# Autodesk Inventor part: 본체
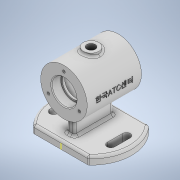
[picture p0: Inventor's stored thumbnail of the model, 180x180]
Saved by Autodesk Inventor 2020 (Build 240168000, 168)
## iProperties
Created: 2021-09
Part Number: 본체
Material: 일반
Document SubType Name: Modeling
Designer: Administrator
Density: 1 g/cm^3
Appearance: 기본값
Mass: 173.2 g
Surface Area: 487.332 cm^2
Volume: 173.2 cm^3
Author: Administrator
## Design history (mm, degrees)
sketch "스케치1"
  geometry: C1 r 52.5 at (0, 0); 1 further point
  constraints: 1 centre point, 1 coincident
  dimensions: "d4" = 105 diameter of C1
extrude "돌출1" new body sketch "스케치1" distance "d1" = 10; taper "d2" = 0 deg
sketch "스케치2"
  geometry: L1 (-81.213, -38.87)-(81.213, -38.87); L2 (81.213, -38.87)-(81.213, 36.13); L3 (81.213, 36.13)-(-81.213, 36.13); L4 (-81.213, 36.13)-(-81.213, -38.87); L5 (-81.213, -38.87)-(81.213, 36.13); L6 (81.213, -38.87)-(-81.213, 36.13); C1 r 52.5 at (0, 0) reference; 6 further points
  constraints: 12 end point, 2 midpoint, 2 parallel, 1 horizontal, 1 perpendicular
  dimensions: "d5" = 75 distance of L2.end L1.end
extrude "돌출2" cut sketch "스케치2" distance "d6" = 10; taper "d7" = 0 deg
sketch "스케치3"
  geometry: C1 r 30 at (0, 62); 1 further point
  constraints: 1 centre point
  dimensions: "d9" = 60 diameter of C1; "d10" = 62 distance of point (0, 0) C1.centre
extrude "돌출3" join sketch "스케치3" stored distance "d11" = 70; taper "d12" = 0 deg
sketch "스케치4"
  geometry: L1 (92, 35)-(32, 35) reference; L2 (62, 35)-(62, -35); L3 (32, -35)-(92, -35) reference; L4 (78, 35)-(78, 23); L5 (78, 23)-(76, 23); L6 (76, 23)-(76, 20); L7 (76, 20)-(87, 20); L8 (87, 20)-(87, -20); L9 (87, -20)-(76, -20); L10 (76, -20)-(76, -23); L11 (76, -23)-(78, -23); L12 (78, -23)-(78, -35); 1 further point
  constraints: 20 end point, 6 perpendicular, 6 point on line, 2 midpoint, 1 vertical
  dimensions: "d13" = 32 diameter of L4 L2; "d14" = 28 diameter of L6 L2; "d15" = 50 diameter of L8 L2; "d16" = 12 distance between parallel lines of L1 L5; "d17" = 12 distance between parallel lines of L3 L11; "d18" = 40 distance between parallel lines of L9 L7; "d19" = 3 distance between parallel lines of L5 L7
revolve "회전1" sketch "스케치4" stored, may be unused: angle "d20" = 90 deg
sketch "스케치5"
  geometry: L1 (-5, 23.63)-(5, 23.63); L2 (5, 23.63)-(5, -26.37); L3 (5, -26.37)-(-5, -26.37); L4 (-5, -26.37)-(-5, 23.63); L5 (35.29, -38.87)-(-35.29, -38.87) reference; A1 r 52.5 centre (0, 0) between (35.29, -38.87) and (38.09, 36.13) reference; A2 r 52.5 centre (0, 0) between (-38.09, 36.13) and (-35.29, -38.87) reference; 1 further point
  constraints: 8 end point, 2 parallel, 1 horizontal, 1 perpendicular
  dimensions: "d21" = 10 distance of L2.end L3.end; "d22" = 50 distance of L1.end L2.end; "d67" = 12.5 distance between parallel lines of L5 L3; "d68" = 47.5 distance edge to line of A2 L4
extrude "돌출4" join sketch "스케치5" stored distance "d11" = 70; taper "d12" = 0 deg; stored distance "d23" = 70; taper "d24" = 0 deg
node "작업 평면2"
  node "작업 평면1"
sketch "스케치6"
  geometry: C1 r 10 at (0, 0); 1 further point
  constraints: 1 centre point, 1 coincident
  dimensions: "d26" = 10 radius of C1
extrude "돌출5" join sketch "스케치6" stored distance "d11" = 70; taper "d12" = 0 deg; stored distance "d27" = 70; taper "d28" = 0 deg
sketch "스케치7"
  geometry: C1 r 10 at (0, 0) reference; 2 further points
  constraints: 1 coincident
hole "구멍1" sketch "스케치7" at (0, 0) diameter "d29" = 10.917; stored, may be unused: countersink angle "d33" = 90 deg, drill point angle "d35" = 0 deg; dims "d30" = 24, "d31" = 4, "d32" = 2, "d34" = 29.1
sketch "스케치8" dims "d36" = 23
  geometry: C1 r 14 at (0, 0) reference; 3 further points
  constraints: 1 coincident, 1 vertical alignment, 2 other
hole "구멍2" sketch "스케치8" at (0, 23) diameter "d37" = 3.45873; stored, may be unused: countersink angle "d41" = 90 deg, drill point angle "d43" = 118 deg; dims "d38" = 8, "d39" = 4, "d40" = 2, "d42" = 10
sketch "스케치9"
  geometry: L1 (-37, 8.63)-(-37, -11.37); L2 (-42, 8.63)-(-42, -11.37); L3 (-32, -11.37)-(-32, 8.63); L4 (-38.09, 36.13)-(38.09, 36.13) reference; A1 r 5 centre (-37, 8.63) between (-32, 8.63) and (-42, 8.63); A2 r 5 centre (-37, -11.37) between (-42, -11.37) and (-32, -11.37); 2 further points
  constraints: 8 end point, 4 point on circle, 4 tangent, 2 centre point, 1 midpoint, 1 parallel, 1 vertical
  dimensions: "d47" = 37 horizontal distance of point (-37, -1.37) point (0, 0); "d48" = 10 distance between parallel lines of L2 L3; "d49" = 20 distance of L1.end L1.start; "d50" = 37.5 distance from line of L4 point (-37, -1.37)
extrude "돌출6" cut sketch "스케치9" distance "d51" = 70; taper "d52" = 0 deg
fillet "모깎기1" dims "d53" = 3
fillet "모깎기2" dims "d54" = 3
fillet "모깎기3" dims "d55" = 3
fillet "모깎기4" dims "d56" = 0.3
chamfer "모따기1" distance "d57" = 1; stored, may be unused: second distance "d58" = 2, angle "d59" = 45 deg
node "작업 평면5"
  node "작업 평면4"
sketch "스케치10"
  geometry: L1 (30, 35)-(-30, 35) reference; L2 (30, -35)-(30, 35) reference; 2 further points
  constraints: 1 other
  dimensions: "d61" = 35 distance from line of L1 point (0, 0); "d62" = 30 distance from line of point (0, 0) L2
feature "엠보싱1" sketch "스케치10" dims "d63" = 0.5, "d64" = 0
fillet "모깎기5" dims "d65" = 3
sketch "스케치11"
  geometry: L1 (7, 38.87)-(0, 38.87) reference; L2 (0, -36.13)-(7, -36.13) reference; 1 further point
node "솔리드1"
pattern_circular "원형 패턴1" dims angle "d45" = 360 deg
mirror "미러1"
mirror "미러2"
node "작업 평면3"
feature "A9D066F2-1C7D-4E18-AEED-F7BC21143FA4" dims "d29" = 10.917, "d30" = 24, "d31" = 4, "d32" = 2, "d33" = 90 deg, "d34" = 29.1, "d35" = 0
other parameters: "d25" = 3, "d60" = 24.5
